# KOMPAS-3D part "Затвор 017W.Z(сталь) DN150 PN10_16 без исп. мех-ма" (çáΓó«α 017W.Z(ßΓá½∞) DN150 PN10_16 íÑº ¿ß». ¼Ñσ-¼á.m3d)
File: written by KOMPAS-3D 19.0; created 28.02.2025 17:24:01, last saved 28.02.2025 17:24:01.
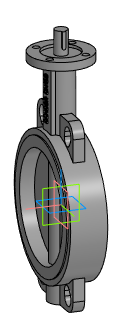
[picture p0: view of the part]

Document properties: Автор: Евгений; Полное имя файла: E:\Dendor Работа Сачек\3D для проекитирвщиков\1.5 Тип 017W.Z Сталь Затвор дисковый поворотный Межфланцевый\stp_Тип 017W.Z(сталь). Затвор без исполн. механизма\Затвор 017W.Z(сталь) DN150 PN10_16 без исп. мех-ма.m3d

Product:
- Part/product: Затвор 017W.Z(сталь) DN150 PN10_16 без исп. мех-ма

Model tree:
1. Операция без истории:1  (labels: Затвор 017W.Z(сталь) DN150 PN10_16 без исп. мех-ма)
